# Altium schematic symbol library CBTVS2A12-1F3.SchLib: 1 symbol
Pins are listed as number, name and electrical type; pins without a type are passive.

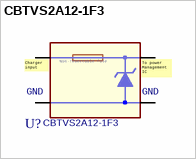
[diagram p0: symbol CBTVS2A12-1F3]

## CBTVS2A12-1F3
designator U?
footprint ST_CSP04N40P2X2_77X77X40
pins: A1 Charger input, A2 To power Management IC, B1 GND, B2 GND1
